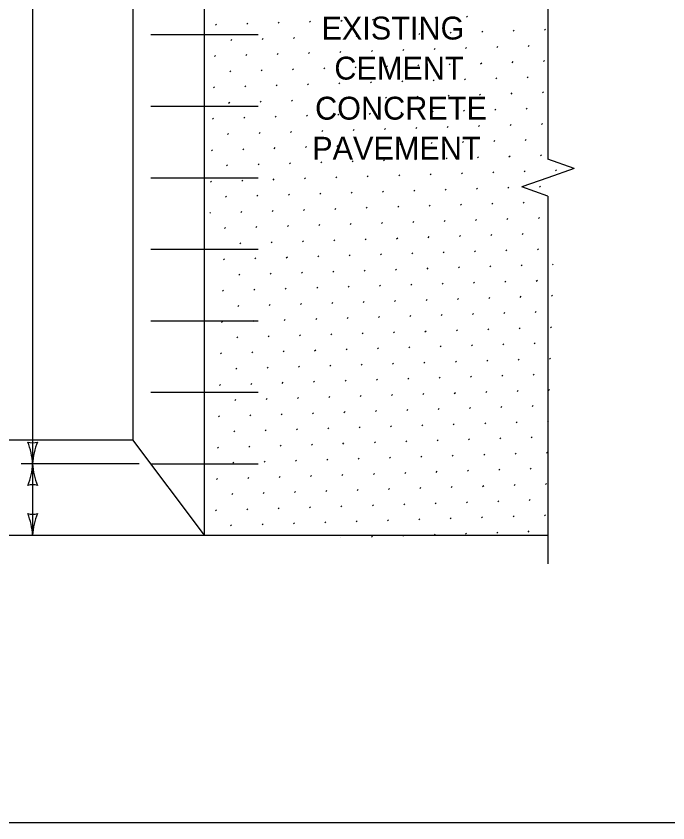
# Model space of a CAD drawing. Extents: x 49991.4 to 50021, y 49987.6 to 50011.4.
# Drawn here: x 50005.45 to 50007.726, y 49987.799 to 49990.619 of the extents above; entities that cross this region are included whole.
import ezdxf

# ---------------------------------------------------------------- set-up
doc = ezdxf.new("R2010")
doc.units = 0
for name, color, linetype in [('Level 1', 7, 'Continuous'), ('Level 10', 7, 'Continuous'), ('Level 2', 7, 'Continuous'), ('Level 3', 7, 'Continuous'), ('Level 4', 7, 'Continuous'), ('Level 6', 7, 'Continuous')]:
    doc.layers.add(name, color=color, linetype=linetype)

msp = doc.modelspace()

# ---------------------------------------------------------------- linework, layer by layer
at = {"layer": 'Level 1'}
for p, q in [((50006.1071, 49988.8039), (50006.1071, 49991.8039)), ((50005.8571, 49991.4706), (50005.8571, 49989.1372)), ((50002.6071, 49989.1372), (50005.8571, 49989.1372)), ((50006.1071, 49988.8039), (50005.8571, 49989.1372)), ((50002.3571, 49988.8039), (50006.1071, 49988.8039)), ((50006.1071, 49988.8039), (50007.3071, 49988.8039))]:
    msp.add_line(p, q, dxfattribs=at)
msp.add_lwpolyline([(49999.3835, 49998.9992), (50016.7501, 49998.9992), (50016.7501, 49987.7988), (49999.3835, 49987.7988)], close=True, dxfattribs=at)
at = {"layer": 'Level 10'}
for p, q in [((50006.4748, 49990.5974), (50006.4783, 49990.601)), ((50006.5844, 49990.601), (50006.588, 49990.6045)), ((50006.694, 49990.6045), (50006.6976, 49990.608)), ((50006.8036, 49990.608), (50006.8072, 49990.6116)), ((50006.9132, 49990.6116), (50006.9168, 49990.6151)), ((50007.0229, 49990.6151), (50007.0264, 49990.6187)), ((50006.146, 49990.5868), (50006.1495, 49990.5903)), ((50006.2556, 49990.5903), (50006.2591, 49990.5939)), ((50006.3652, 49990.5939), (50006.3687, 49990.5974)), ((50007.2951, 49990.5692), (50007.2986, 49990.5727)), ((50006.4182, 49990.5408), (50006.4218, 49990.5444)), ((50006.5278, 49990.5444), (50006.5314, 49990.5479)), ((50006.6375, 49990.5479), (50006.641, 49990.5515)), ((50006.7471, 49990.5515), (50006.7506, 49990.555)), ((50006.8567, 49990.555), (50006.8602, 49990.5585)), ((50006.9663, 49990.5586), (50006.9698, 49990.5621)), ((50007.0759, 49990.5621), (50007.0794, 49990.5656)), ((50007.1855, 49990.5656), (50007.189, 49990.5692)), ((50006.199, 49990.5338), (50006.2026, 49990.5373)), ((50006.3086, 49990.5373), (50006.3122, 49990.5408)), ((50007.2385, 49990.5126), (50007.2421, 49990.5161)), ((50006.3617, 49990.4843), (50006.3652, 49990.4878)), ((50006.4713, 49990.4878), (50006.4748, 49990.4913)), ((50006.5809, 49990.4914), (50006.5844, 49990.4949)), ((50006.6905, 49990.4949), (50006.694, 49990.4984)), ((50006.8001, 49990.4984), (50006.8036, 49990.502)), ((50006.9097, 49990.502), (50006.9132, 49990.5055)), ((50007.0193, 49990.5055), (50007.0228, 49990.5091)), ((50007.1289, 49990.5091), (50007.1325, 49990.5126)), ((50006.1424, 49990.4772), (50006.146, 49990.4807)), ((50006.252, 49990.4807), (50006.2556, 49990.4843)), ((50007.182, 49990.456), (50007.1855, 49990.4596)), ((50007.2916, 49990.4596), (50007.2951, 49990.4631)), ((50006.3051, 49990.4277), (50006.3086, 49990.4312)), ((50006.4147, 49990.4312), (50006.4182, 49990.4348)), ((50006.5243, 49990.4348), (50006.5278, 49990.4383)), ((50006.6339, 49990.4383), (50006.6374, 49990.4419)), ((50006.7435, 49990.4419), (50006.7471, 49990.4454)), ((50006.8531, 49990.4454), (50006.8567, 49990.4489)), ((50006.9627, 49990.4489), (50006.9663, 49990.4525)), ((50007.0723, 49990.4525), (50007.0759, 49990.456)), ((50006.1955, 49990.4241), (50006.199, 49990.4277)), ((50007.1254, 49990.3995), (50007.1289, 49990.403)), ((50007.235, 49990.403), (50007.2385, 49990.4065)), ((50006.2485, 49990.3711), (50006.252, 49990.3747)), ((50006.3581, 49990.3747), (50006.3617, 49990.3782)), ((50006.4677, 49990.3782), (50006.4713, 49990.3817)), ((50006.5773, 49990.3817), (50006.5809, 49990.3853)), ((50006.6869, 49990.3853), (50006.6905, 49990.3888)), ((50006.7965, 49990.3888), (50006.8001, 49990.3924)), ((50006.9062, 49990.3924), (50006.9097, 49990.3959)), ((50007.0158, 49990.3959), (50007.0193, 49990.3994)), ((50006.1389, 49990.3676), (50006.1424, 49990.3711)), ((50007.0688, 49990.3429), (50007.0723, 49990.3464)), ((50007.1784, 49990.3464), (50007.1819, 49990.35)), ((50007.288, 49990.35), (50007.2916, 49990.3535)), ((50006.1919, 49990.3145), (50006.1955, 49990.3181)), ((50006.3015, 49990.3181), (50006.3051, 49990.3216)), ((50006.4111, 49990.3216), (50006.4147, 49990.3252)), ((50006.5208, 49990.3252), (50006.5243, 49990.3287)), ((50006.6304, 49990.3287), (50006.6339, 49990.3322)), ((50006.74, 49990.3323), (50006.7435, 49990.3358)), ((50006.8496, 49990.3358), (50006.8531, 49990.3393)), ((50006.9592, 49990.3393), (50006.9627, 49990.3429)), ((50007.0122, 49990.2863), (50007.0158, 49990.2898)), ((50007.1218, 49990.2898), (50007.1254, 49990.2934)), ((50007.2314, 49990.2934), (50007.235, 49990.2969)), ((50006.1354, 49990.258), (50006.1389, 49990.2615)), ((50006.245, 49990.2615), (50006.2485, 49990.265)), ((50006.3546, 49990.265), (50006.3581, 49990.2686)), ((50006.4642, 49990.2686), (50006.4677, 49990.2721)), ((50006.5738, 49990.2721), (50006.5773, 49990.2757)), ((50006.6834, 49990.2757), (50006.6869, 49990.2792)), ((50006.793, 49990.2792), (50006.7965, 49990.2828)), ((50006.9026, 49990.2828), (50006.9062, 49990.2863)), ((50006.9556, 49990.2297), (50006.9592, 49990.2333)), ((50007.0653, 49990.2333), (50007.0688, 49990.2368)), ((50007.1749, 49990.2368), (50007.1784, 49990.2404)), ((50007.2845, 49990.2404), (50007.288, 49990.2439)), ((50006.1884, 49990.2049), (50006.1919, 49990.2085)), ((50006.298, 49990.2085), (50006.3015, 49990.212)), ((50006.4076, 49990.212), (50006.4111, 49990.2156)), ((50006.5172, 49990.2156), (50006.5207, 49990.2191)), ((50006.6268, 49990.2191), (50006.6304, 49990.2226)), ((50006.7364, 49990.2226), (50006.74, 49990.2262)), ((50006.846, 49990.2262), (50006.8496, 49990.2297)), ((50006.8991, 49990.1732), (50006.9026, 49990.1767)), ((50007.0087, 49990.1767), (50007.0122, 49990.1802)), ((50007.1183, 49990.1802), (50007.1218, 49990.1838)), ((50007.2279, 49990.1838), (50007.2314, 49990.1873)), ((50006.1318, 49990.1484), (50006.1353, 49990.1519)), ((50006.2414, 49990.1519), (50006.245, 49990.1554)), ((50006.351, 49990.1554), (50006.3546, 49990.159)), ((50006.4606, 49990.159), (50006.4642, 49990.1625)), ((50006.5702, 49990.1625), (50006.5738, 49990.1661)), ((50006.6799, 49990.1661), (50006.6834, 49990.1696)), ((50006.7895, 49990.1696), (50006.793, 49990.1731)), ((50006.8425, 49990.1166), (50006.846, 49990.1201)), ((50006.9521, 49990.1201), (50006.9556, 49990.1237)), ((50007.0617, 49990.1237), (50007.0653, 49990.1272)), ((50007.1713, 49990.1272), (50007.1749, 49990.1307)), ((50007.2809, 49990.1307), (50007.2845, 49990.1343)), ((50006.1848, 49990.0953), (50006.1884, 49990.0989)), ((50006.2945, 49990.0989), (50006.298, 49990.1024)), ((50006.4041, 49990.1024), (50006.4076, 49990.1059)), ((50006.5137, 49990.106), (50006.5172, 49990.1095)), ((50006.6233, 49990.1095), (50006.6268, 49990.113)), ((50006.7329, 49990.113), (50006.7364, 49990.1166)), ((50006.7859, 49990.06), (50006.7895, 49990.0635)), ((50006.8955, 49990.0635), (50006.8991, 49990.0671)), ((50007.0051, 49990.0671), (50007.0087, 49990.0706)), ((50007.1147, 49990.0706), (50007.1183, 49990.0742)), ((50007.2244, 49990.0742), (50007.2279, 49990.0777)), ((50007.334, 49990.0777), (50007.3375, 49990.0813)), ((50006.1283, 49990.0387), (50006.1318, 49990.0423)), ((50006.2379, 49990.0423), (50006.2414, 49990.0458)), ((50006.3475, 49990.0458), (50006.351, 49990.0494)), ((50006.4571, 49990.0494), (50006.4606, 49990.0529)), ((50006.5667, 49990.0529), (50006.5702, 49990.0565)), ((50006.6763, 49990.0565), (50006.6798, 49990.06)), ((50006.7293, 49990.0034), (50006.7329, 49990.007)), ((50006.839, 49990.007), (50006.8425, 49990.0105)), ((50006.9486, 49990.0105), (50006.9521, 49990.014)), ((50007.0582, 49990.0141), (50007.0617, 49990.0176)), ((50007.1678, 49990.0176), (50007.1713, 49990.0211)), ((50007.2774, 49990.0211), (50007.2809, 49990.0247)), ((50006.1813, 49989.9857), (50006.1848, 49989.9892)), ((50006.2909, 49989.9893), (50006.2944, 49989.9928)), ((50006.4005, 49989.9928), (50006.4041, 49989.9963)), ((50006.5101, 49989.9963), (50006.5137, 49989.9999)), ((50006.6197, 49989.9999), (50006.6233, 49990.0034)), ((50006.6728, 49989.9469), (50006.6763, 49989.9504)), ((50006.7824, 49989.9504), (50006.7859, 49989.9539)), ((50006.892, 49989.9539), (50006.8955, 49989.9575)), ((50007.0016, 49989.9575), (50007.0051, 49989.961)), ((50007.1112, 49989.961), (50007.1147, 49989.9646)), ((50007.2208, 49989.9646), (50007.2243, 49989.9681)), ((50006.1261, 49989.9305), (50006.1283, 49989.9327)), ((50006.2343, 49989.9327), (50006.2379, 49989.9362)), ((50006.3439, 49989.9362), (50006.3475, 49989.9398)), ((50006.4536, 49989.9398), (50006.4571, 49989.9433)), ((50006.5632, 49989.9433), (50006.5667, 49989.9468)), ((50006.6162, 49989.8903), (50006.6197, 49989.8938)), ((50006.7258, 49989.8938), (50006.7293, 49989.8974)), ((50006.8354, 49989.8974), (50006.8389, 49989.9009)), ((50006.945, 49989.9009), (50006.9486, 49989.9044)), ((50007.0546, 49989.9044), (50007.0582, 49989.908)), ((50007.1642, 49989.908), (50007.1678, 49989.9115)), ((50007.2738, 49989.9115), (50007.2774, 49989.9151)), ((50006.1778, 49989.8761), (50006.1813, 49989.8796)), ((50006.2874, 49989.8796), (50006.2909, 49989.8832)), ((50006.397, 49989.8832), (50006.4005, 49989.8867)), ((50006.5066, 49989.8867), (50006.5101, 49989.8903)), ((50006.5596, 49989.8337), (50006.5632, 49989.8372)), ((50006.6692, 49989.8372), (50006.6728, 49989.8408)), ((50006.7788, 49989.8408), (50006.7824, 49989.8443)), ((50006.8884, 49989.8443), (50006.892, 49989.8479)), ((50006.9981, 49989.8479), (50007.0016, 49989.8514)), ((50007.1077, 49989.8514), (50007.1112, 49989.8549)), ((50007.2173, 49989.855), (50007.2208, 49989.8585)), ((50006.2308, 49989.8231), (50006.2343, 49989.8266)), ((50006.3404, 49989.8266), (50006.3439, 49989.8302)), ((50006.45, 49989.8302), (50006.4535, 49989.8337)), ((50006.503, 49989.7771), (50006.5066, 49989.7807)), ((50006.6127, 49989.7807), (50006.6162, 49989.7842)), ((50006.7223, 49989.7842), (50006.7258, 49989.7877)), ((50006.8319, 49989.7878), (50006.8354, 49989.7913)), ((50006.9415, 49989.7913), (50006.945, 49989.7948)), ((50007.0511, 49989.7948), (50007.0546, 49989.7984)), ((50007.1607, 49989.7984), (50007.1642, 49989.8019)), ((50007.2703, 49989.8019), (50007.2738, 49989.8055)), ((50006.1742, 49989.7665), (50006.1778, 49989.77)), ((50006.2838, 49989.77), (50006.2874, 49989.7736)), ((50006.3934, 49989.7736), (50006.397, 49989.7771)), ((50006.5561, 49989.7241), (50006.5596, 49989.7276)), ((50006.6657, 49989.7276), (50006.6692, 49989.7312)), ((50006.7753, 49989.7312), (50006.7788, 49989.7347)), ((50006.8849, 49989.7347), (50006.8884, 49989.7383)), ((50006.9945, 49989.7383), (50006.998, 49989.7418)), ((50007.1041, 49989.7418), (50007.1077, 49989.7453)), ((50007.2137, 49989.7453), (50007.2173, 49989.7489)), ((50007.3233, 49989.7489), (50007.3261, 49989.7516)), ((50006.2273, 49989.7135), (50006.2308, 49989.717)), ((50006.3369, 49989.717), (50006.3404, 49989.7205)), ((50006.4465, 49989.7205), (50006.45, 49989.7241)), ((50006.4995, 49989.6675), (50006.503, 49989.6711)), ((50006.6091, 49989.6711), (50006.6126, 49989.6746)), ((50006.7187, 49989.6746), (50006.7223, 49989.6781)), ((50006.8283, 49989.6781), (50006.8319, 49989.6817)), ((50006.9379, 49989.6817), (50006.9415, 49989.6852)), ((50007.0475, 49989.6852), (50007.0511, 49989.6888)), ((50007.1572, 49989.6888), (50007.1607, 49989.6923)), ((50007.2668, 49989.6923), (50007.2703, 49989.6958)), ((50006.1707, 49989.6569), (50006.1742, 49989.6604)), ((50006.2803, 49989.6604), (50006.2838, 49989.664)), ((50006.3899, 49989.664), (50006.3934, 49989.6675)), ((50007.3198, 49989.6393), (50007.3233, 49989.6428)), ((50006.4429, 49989.6109), (50006.4465, 49989.6145)), ((50006.5525, 49989.6145), (50006.5561, 49989.618)), ((50006.6621, 49989.618), (50006.6657, 49989.6216)), ((50006.7718, 49989.6216), (50006.7753, 49989.6251)), ((50006.8814, 49989.6251), (50006.8849, 49989.6286)), ((50006.991, 49989.6287), (50006.9945, 49989.6322)), ((50007.1006, 49989.6322), (50007.1041, 49989.6357)), ((50007.2102, 49989.6357), (50007.2137, 49989.6393)), ((50006.2237, 49989.6039), (50006.2272, 49989.6074)), ((50006.3333, 49989.6074), (50006.3369, 49989.6109)), ((50007.2632, 49989.5827), (50007.2668, 49989.5862)), ((50006.3863, 49989.5544), (50006.3899, 49989.5579)), ((50006.496, 49989.5579), (50006.4995, 49989.5614)), ((50006.6056, 49989.5614), (50006.6091, 49989.565)), ((50006.7152, 49989.565), (50006.7187, 49989.5685)), ((50006.8248, 49989.5685), (50006.8283, 49989.5721)), ((50006.9344, 49989.5721), (50006.9379, 49989.5756)), ((50007.044, 49989.5756), (50007.0475, 49989.5792)), ((50007.1536, 49989.5792), (50007.1571, 49989.5827)), ((50006.1671, 49989.5473), (50006.1707, 49989.5508)), ((50006.2767, 49989.5508), (50006.2803, 49989.5544)), ((50007.2066, 49989.5261), (50007.2102, 49989.5297)), ((50007.3163, 49989.5297), (50007.3198, 49989.5332)), ((50006.3298, 49989.4978), (50006.3333, 49989.5013)), ((50006.4394, 49989.5013), (50006.4429, 49989.5049)), ((50006.549, 49989.5049), (50006.5525, 49989.5084)), ((50006.6586, 49989.5084), (50006.6621, 49989.512)), ((50006.7682, 49989.512), (50006.7717, 49989.5155)), ((50006.8778, 49989.5155), (50006.8814, 49989.519)), ((50006.9874, 49989.519), (50006.991, 49989.5226)), ((50007.097, 49989.5226), (50007.1006, 49989.5261)), ((50006.2202, 49989.4942), (50006.2237, 49989.4978)), ((50007.1501, 49989.4696), (50007.1536, 49989.4731)), ((50007.2597, 49989.4731), (50007.2632, 49989.4766)), ((50006.2732, 49989.4412), (50006.2767, 49989.4447)), ((50006.3828, 49989.4448), (50006.3863, 49989.4483)), ((50006.4924, 49989.4483), (50006.496, 49989.4518)), ((50006.602, 49989.4518), (50006.6056, 49989.4554)), ((50006.7116, 49989.4554), (50006.7152, 49989.4589)), ((50006.8212, 49989.4589), (50006.8248, 49989.4625)), ((50006.9309, 49989.4625), (50006.9344, 49989.466)), ((50007.0405, 49989.466), (50007.044, 49989.4695)), ((50006.1636, 49989.4377), (50006.1671, 49989.4412)), ((50007.0935, 49989.413), (50007.097, 49989.4165)), ((50007.2031, 49989.4165), (50007.2066, 49989.4201)), ((50007.3127, 49989.4201), (50007.3162, 49989.4236)), ((50006.2166, 49989.3846), (50006.2202, 49989.3882)), ((50006.3262, 49989.3882), (50006.3298, 49989.3917)), ((50006.4358, 49989.3917), (50006.4394, 49989.3953)), ((50006.5454, 49989.3953), (50006.549, 49989.3988)), ((50006.6551, 49989.3988), (50006.6586, 49989.4023)), ((50006.7647, 49989.4024), (50006.7682, 49989.4059)), ((50006.8743, 49989.4059), (50006.8778, 49989.4094)), ((50006.9839, 49989.4094), (50006.9874, 49989.413)), ((50007.0369, 49989.3564), (50007.0405, 49989.3599)), ((50007.1465, 49989.3599), (50007.1501, 49989.3635)), ((50007.2561, 49989.3635), (50007.2597, 49989.367)), ((50006.16, 49989.3281), (50006.1636, 49989.3316)), ((50006.2697, 49989.3316), (50006.2732, 49989.3351)), ((50006.3793, 49989.3351), (50006.3828, 49989.3387)), ((50006.4889, 49989.3387), (50006.4924, 49989.3422)), ((50006.5985, 49989.3422), (50006.602, 49989.3458)), ((50006.7081, 49989.3458), (50006.7116, 49989.3493)), ((50006.8177, 49989.3493), (50006.8212, 49989.3529)), ((50006.9273, 49989.3529), (50006.9308, 49989.3564)), ((50006.9803, 49989.2998), (50006.9839, 49989.3034)), ((50007.0899, 49989.3034), (50007.0935, 49989.3069)), ((50007.1996, 49989.3069), (50007.2031, 49989.3104)), ((50007.3092, 49989.3105), (50007.3127, 49989.314)), ((50006.2131, 49989.275), (50006.2166, 49989.2786)), ((50006.3227, 49989.2786), (50006.3262, 49989.2821)), ((50006.4323, 49989.2821), (50006.4358, 49989.2856)), ((50006.5419, 49989.2857), (50006.5454, 49989.2892)), ((50006.6515, 49989.2892), (50006.6551, 49989.2927)), ((50006.7611, 49989.2927), (50006.7647, 49989.2963)), ((50006.8707, 49989.2963), (50006.8743, 49989.2998)), ((50006.9238, 49989.2433), (50006.9273, 49989.2468)), ((50007.0334, 49989.2468), (50007.0369, 49989.2503)), ((50007.143, 49989.2503), (50007.1465, 49989.2539)), ((50007.2526, 49989.2539), (50007.2561, 49989.2574)), ((50006.1565, 49989.2185), (50006.16, 49989.222)), ((50006.2661, 49989.222), (50006.2696, 49989.2255)), ((50006.3757, 49989.2255), (50006.3793, 49989.2291)), ((50006.4853, 49989.2291), (50006.4889, 49989.2326)), ((50006.5949, 49989.2326), (50006.5985, 49989.2362)), ((50006.7045, 49989.2362), (50006.7081, 49989.2397)), ((50006.8142, 49989.2397), (50006.8177, 49989.2432)), ((50006.8672, 49989.1867), (50006.8707, 49989.1902)), ((50006.9768, 49989.1902), (50006.9803, 49989.1938)), ((50007.0864, 49989.1938), (50007.0899, 49989.1973)), ((50007.196, 49989.1973), (50007.1996, 49989.2008)), ((50007.3056, 49989.2008), (50007.3092, 49989.2044)), ((50006.2095, 49989.1654), (50006.2131, 49989.169)), ((50006.3191, 49989.169), (50006.3227, 49989.1725)), ((50006.4288, 49989.1725), (50006.4323, 49989.176)), ((50006.5384, 49989.176), (50006.5419, 49989.1796)), ((50006.648, 49989.1796), (50006.6515, 49989.1831)), ((50006.7576, 49989.1831), (50006.7611, 49989.1867)), ((50006.8106, 49989.1301), (50006.8141, 49989.1336)), ((50006.9202, 49989.1336), (50006.9238, 49989.1372)), ((50007.0298, 49989.1372), (50007.0334, 49989.1407)), ((50007.1394, 49989.1407), (50007.143, 49989.1443)), ((50007.249, 49989.1443), (50007.2526, 49989.1478)), ((50006.153, 49989.1088), (50006.1565, 49989.1124)), ((50006.2626, 49989.1124), (50006.2661, 49989.1159)), ((50006.3722, 49989.1159), (50006.3757, 49989.1195)), ((50006.4818, 49989.1195), (50006.4853, 49989.123)), ((50006.5914, 49989.123), (50006.5949, 49989.1266)), ((50006.701, 49989.1266), (50006.7045, 49989.1301)), ((50006.754, 49989.0735), (50006.7576, 49989.0771)), ((50006.8636, 49989.0771), (50006.8672, 49989.0806)), ((50006.9733, 49989.0806), (50006.9768, 49989.0841)), ((50007.0829, 49989.0842), (50007.0864, 49989.0877)), ((50007.1925, 49989.0877), (50007.196, 49989.0912)), ((50007.3021, 49989.0912), (50007.3056, 49989.0948)), ((50006.206, 49989.0558), (50006.2095, 49989.0593)), ((50006.3156, 49989.0594), (50006.3191, 49989.0629)), ((50006.4252, 49989.0629), (50006.4287, 49989.0664)), ((50006.5348, 49989.0664), (50006.5384, 49989.07)), ((50006.6444, 49989.07), (50006.648, 49989.0735)), ((50006.6975, 49989.0169), (50006.701, 49989.0205)), ((50006.8071, 49989.0205), (50006.8106, 49989.024)), ((50006.9167, 49989.024), (50006.9202, 49989.0276)), ((50007.0263, 49989.0276), (50007.0298, 49989.0311)), ((50007.1359, 49989.0311), (50007.1394, 49989.0347)), ((50007.2455, 49989.0347), (50007.249, 49989.0382)), ((50006.1494, 49988.9992), (50006.153, 49989.0028)), ((50006.259, 49989.0028), (50006.2626, 49989.0063)), ((50006.3686, 49989.0063), (50006.3722, 49989.0099)), ((50006.4782, 49989.0099), (50006.4818, 49989.0134)), ((50006.5879, 49989.0134), (50006.5914, 49989.0169)), ((50006.6409, 49988.9604), (50006.6444, 49988.9639)), ((50006.7505, 49988.9639), (50006.754, 49988.9675)), ((50006.8601, 49988.9675), (50006.8636, 49988.971)), ((50006.9697, 49988.971), (50006.9732, 49988.9745)), ((50007.0793, 49988.9745), (50007.0829, 49988.9781)), ((50007.1889, 49988.9781), (50007.1925, 49988.9816)), ((50007.2985, 49988.9816), (50007.3021, 49988.9852)), ((50006.2025, 49988.9462), (50006.206, 49988.9497)), ((50006.3121, 49988.9497), (50006.3156, 49988.9533)), ((50006.4217, 49988.9533), (50006.4252, 49988.9568)), ((50006.5313, 49988.9568), (50006.5348, 49988.9604)), ((50006.5843, 49988.9038), (50006.5878, 49988.9073)), ((50006.6939, 49988.9073), (50006.6975, 49988.9109)), ((50006.8035, 49988.9109), (50006.8071, 49988.9144)), ((50006.9131, 49988.9144), (50006.9167, 49988.918)), ((50007.0227, 49988.918), (50007.0263, 49988.9215)), ((50007.1324, 49988.9215), (50007.1359, 49988.925)), ((50007.242, 49988.9251), (50007.2455, 49988.9286)), ((50006.1459, 49988.8896), (50006.1494, 49988.8932)), ((50006.2555, 49988.8932), (50006.259, 49988.8967)), ((50006.3651, 49988.8967), (50006.3686, 49988.9002)), ((50006.4747, 49988.9003), (50006.4782, 49988.9038)), ((50006.5277, 49988.8472), (50006.5313, 49988.8508)), ((50006.6373, 49988.8508), (50006.6409, 49988.8543)), ((50006.747, 49988.8543), (50006.7505, 49988.8578)), ((50006.8566, 49988.8579), (50006.8601, 49988.8614)), ((50006.9662, 49988.8614), (50006.9697, 49988.8649)), ((50007.0758, 49988.8649), (50007.0793, 49988.8685)), ((50007.1854, 49988.8685), (50007.1889, 49988.872)), ((50007.295, 49988.872), (50007.2985, 49988.8756)), ((50006.1989, 49988.8366), (50006.2024, 49988.8401)), ((50006.3085, 49988.8401), (50006.3121, 49988.8437)), ((50006.4181, 49988.8437), (50006.4217, 49988.8472)), ((50006.584, 49988.7974), (50006.5843, 49988.7977)), ((50006.6904, 49988.7977), (50006.6939, 49988.8013)), ((50006.8, 49988.8013), (50006.8035, 49988.8048)), ((50006.9096, 49988.8048), (50006.9131, 49988.8084)), ((50007.0192, 49988.8084), (50007.0227, 49988.8119)), ((50007.1288, 49988.8119), (50007.1323, 49988.8154)), ((50007.2384, 49988.8154), (50007.242, 49988.819))]:
    msp.add_line(p, q, dxfattribs=at)
at = {"layer": 'Level 3'}
for p, q in [((50005.5071, 49991.5539), (50005.5071, 49989.0539)), ((50005.8796, 49989.0539), (50005.4671, 49989.0539)), ((50005.5071, 49989.0539), (50005.5071, 49988.8039))]:
    msp.add_line(p, q, dxfattribs=at)
for centre, radius, start, end in [((50005.5071, 49989.1821), 0.0548, 252.1388, 287.8612), ((50005.2743, 49989.0424), 0.233, 2.8273, 22.0772), ((50005.7292, 49989.0447), 0.2223, 157.456, 177.6395), ((50005.2849, 49989.063), 0.2223, 337.456, 357.6395), ((50005.7398, 49989.0654), 0.233, 182.8273, 202.0772), ((50005.5071, 49988.9257), 0.0548, 72.1388, 107.8612), ((50005.5071, 49988.9321), 0.0548, 252.1388, 287.8612), ((50005.2743, 49988.7924), 0.233, 2.8273, 22.0772), ((50005.7292, 49988.7947), 0.2223, 157.456, 177.6395)]:
    msp.add_arc(centre, radius, start, end, dxfattribs=at)
at = {"layer": 'Level 4'}
for p, q in [((50005.9196, 49990.5539), (50006.2946, 49990.5539)), ((50005.9196, 49990.3039), (50006.2946, 49990.3039)), ((50005.9196, 49990.0539), (50006.2946, 49990.0539)), ((50005.9196, 49989.8039), (50006.2946, 49989.8039)), ((50005.9196, 49989.5539), (50006.2946, 49989.5539)), ((50005.9196, 49989.3039), (50006.2946, 49989.3039)), ((50005.9196, 49989.0539), (50006.2946, 49989.0539))]:
    msp.add_line(p, q, dxfattribs=at)
at = {"layer": 'Level 6'}
for p, q in [((50007.3071, 49991.4891), (50007.3071, 49990.1187)), ((50007.3985, 49990.0863), (50007.3071, 49990.1187)), ((50007.3985, 49990.0863), (50007.3071, 49990.0539)), ((50007.3071, 49990.0539), (50007.2157, 49990.0215)), ((50007.3071, 49989.9891), (50007.2157, 49990.0215)), ((50007.3071, 49989.9891), (50007.3071, 49988.7039))]:
    msp.add_line(p, q, dxfattribs=at)

# ---------------------------------------------------------------- texts
at = {"layer": 'Level 2'}
for s, p in [('EXISTING', (50006.5162, 49990.5369)), ('CEMENT', (50006.5611, 49990.3969)), ('CONCRETE', (50006.4938, 49990.2569)), ('PAVEMENT', (50006.4837, 49990.1169))]:
    msp.add_text(s, height=0.08, dxfattribs=at).set_placement(p)

doc.saveas('drawing.dxf')
